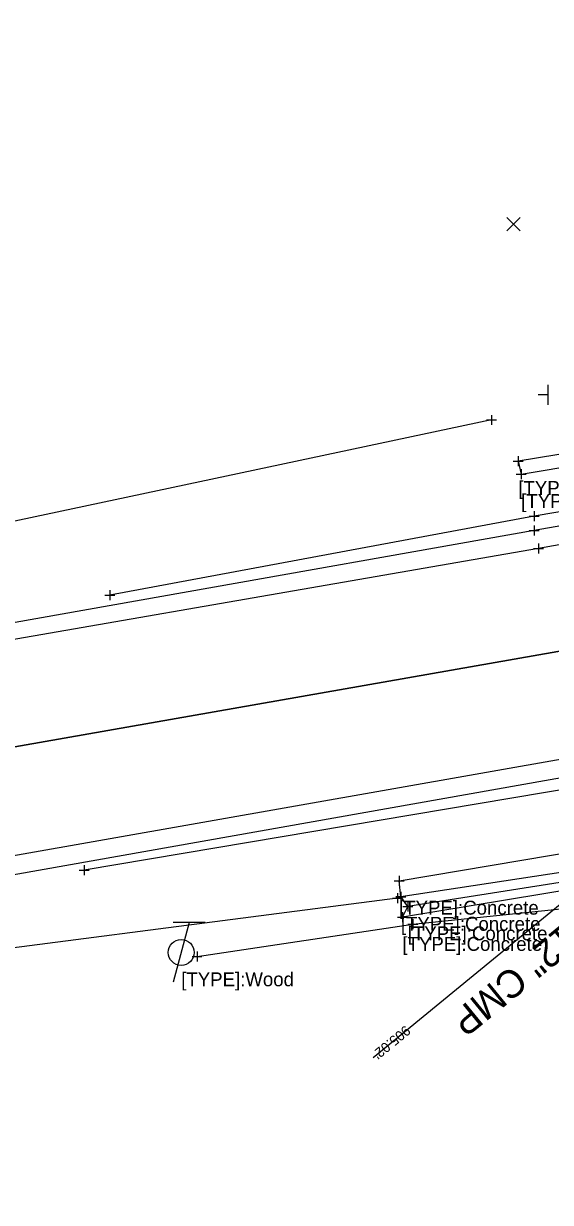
# Model space of a CAD drawing. Extents: x 1386013 to 1389776, y 604170 to 607009.
# Drawn here: x 1388473.5 to 1388526.5, y 604949.8 to 605068.3 of the extents above; entities that cross this region are included whole.
import ezdxf

# ---------------------------------------------------------------- set-up
doc = ezdxf.new("R2010")
doc.units = 0
for name, color, linetype in [('DR_X_Headwall', 7, 'Continuous'), ('DR_X_Storm_Sewer', 7, 'Continuous'), ('DR_X_Text', 7, 'Continuous'), ('DV_X_Text', 7, 'Continuous'), ('PM_X_CL_Double_Solid', 7, 'Continuous'), ('PV_X_COP', 7, 'Continuous'), ('PV_X_EOP', 7, 'Continuous'), ('PV_X_Shoulder', 7, 'Continuous'), ('RD_X_Concrete_Pad', 7, 'Continuous'), ('RD_X_GR_Lt', 7, 'Continuous'), ('RD_X_GR_Rt', 7, 'Continuous'), ('SC_Scratch1', 7, 'Continuous'), ('SV_X_Break_Lines', 7, 'Continuous'), ('SV_X_Random_Point', 7, 'Continuous'), ('SV_X_Text', 7, 'Continuous'), ('SV_X_Toe_of_Slope', 7, 'Continuous'), ('UT_X_Telecom_Cells', 7, 'Continuous')]:
    doc.layers.add(name, color=color, linetype=linetype)

msp = doc.modelspace()

# ---------------------------------------------------------------- linework, layer by layer
at = {"layer": 'DR_X_Headwall'}
msp.add_lwpolyline([(1388523.22, 605024.36), (1388523.51, 605023.05), (1388554.92, 605028.29), (1388554.72, 605029.52)], close=True, dxfattribs=at)
at = {"layer": 'DR_X_Storm_Sewer'}
msp.add_line((1388532.96, 604984.31), (1388508.62, 604964.38), dxfattribs=at)
at = {"layer": 'DV_X_Text'}
for p, q in [((1388520.02, 605028.49), (1388521.02, 605028.49)), ((1388520.52, 605028.99), (1388520.52, 605027.99)), ((1388520.52, 605028.49), (1388520.52, 605028.49)), ((1388523.22, 605024.86), (1388523.22, 605023.86)), ((1388522.72, 605024.36), (1388523.72, 605024.36)), ((1388523.22, 605024.36), (1388523.22, 605024.36)), ((1388523.51, 605023.55), (1388523.51, 605022.55)), ((1388523.01, 605023.05), (1388524.01, 605023.05)), ((1388523.51, 605023.05), (1388523.51, 605023.05)), ((1388524.31, 605018.82), (1388525.31, 605018.82)), ((1388524.81, 605019.32), (1388524.81, 605018.32)), ((1388524.81, 605018.82), (1388524.81, 605018.82)), ((1388524.83, 605017.88), (1388524.83, 605016.88)), ((1388524.33, 605017.38), (1388525.33, 605017.38)), ((1388524.83, 605017.38), (1388524.83, 605017.38)), ((1388524.76, 605015.57), (1388525.76, 605015.57)), ((1388525.26, 605016.07), (1388525.26, 605015.07)), ((1388525.26, 605015.57), (1388525.26, 605015.57)), ((1388481.63, 605010.89), (1388482.63, 605010.89)), ((1388482.13, 605011.39), (1388482.13, 605010.39)), ((1388482.13, 605010.89), (1388482.13, 605010.89)), ((1388479.07, 604983.23), (1388480.07, 604983.23)), ((1388479.57, 604983.73), (1388479.57, 604982.73)), ((1388479.57, 604983.23), (1388479.57, 604983.23)), ((1388510.73, 604982.16), (1388511.73, 604982.16)), ((1388511.23, 604982.66), (1388511.23, 604981.66)), ((1388511.23, 604982.16), (1388511.23, 604982.16)), ((1388511.07, 604980.92), (1388511.07, 604979.92)), ((1388511.41, 604981.07), (1388511.41, 604980.07)), ((1388511.41, 604981.04), (1388511.41, 604980.04)), ((1388510.57, 604980.42), (1388511.57, 604980.42)), ((1388510.91, 604980.57), (1388511.91, 604980.57)), ((1388510.91, 604980.54), (1388511.91, 604980.54)), ((1388511.07, 604980.42), (1388511.07, 604980.42)), ((1388511.41, 604980.57), (1388511.41, 604980.57)), ((1388511.41, 604980.54), (1388511.41, 604980.54)), ((1388512.1, 604980.09), (1388512.1, 604979.09)), ((1388512.11, 604980.08), (1388512.11, 604979.08)), ((1388511.07, 604978.52), (1388512.07, 604978.52)), ((1388511.57, 604979.02), (1388511.57, 604978.02)), ((1388511.57, 604978.52), (1388511.57, 604978.52)), ((1388511.6, 604979.59), (1388512.6, 604979.59)), ((1388511.61, 604979.58), (1388512.61, 604979.58)), ((1388512.1, 604979.59), (1388512.1, 604979.59)), ((1388512.11, 604979.58), (1388512.11, 604979.58)), ((1388512.12, 604977.8), (1388513.12, 604977.8)), ((1388512.62, 604978.3), (1388512.62, 604977.3)), ((1388512.62, 604977.8), (1388512.62, 604977.8)), ((1388490.91, 604975.05), (1388490.91, 604974.05)), ((1388490.41, 604974.55), (1388491.41, 604974.55)), ((1388490.91, 604974.55), (1388490.91, 604974.55))]:
    msp.add_line(p, q, dxfattribs=at)
at = {"layer": 'PM_X_CL_Double_Solid'}
msp.add_lwpolyline([(1387998.85, 604914.97), (1388072.27, 604927.44), (1388150.34, 604940.54), (1388219.83, 604952.56), (1388327.21, 604971.05), (1388378.93, 604979.71), (1388451.75, 604991.99), (1388527.19, 605005.2), (1388605.28, 605019.17), (1388650.04, 605026.96), (1388727.22, 605040.35), (1388785.55, 605050.58), (1388850.55, 605062.12), (1388924.49, 605075.02), (1388990.9, 605086.8), (1389068.68, 605100.88), (1389141.9, 605114.3), (1389207.53, 605126.39), (1389280.37, 605139.49)], dxfattribs=at)
at = {"layer": 'PV_X_COP'}
msp.add_lwpolyline([(1389280.37, 605139.49), (1389207.53, 605126.39), (1389141.9, 605114.3), (1389068.68, 605100.88), (1388990.9, 605086.8), (1388924.49, 605075.02), (1388850.55, 605062.12), (1388785.55, 605050.58), (1388727.22, 605040.35), (1388650.04, 605026.96), (1388605.28, 605019.17), (1388527.19, 605005.2), (1388451.75, 604991.99), (1388378.93, 604979.71), (1388327.21, 604971.05), (1388219.83, 604952.56), (1388150.34, 604940.54), (1388072.27, 604927.44), (1387998.85, 604914.97)], dxfattribs=at)
at = {"layer": 'PV_X_EOP'}
for points in [[(1389278.61, 605149.89), (1389205.62, 605136.54), (1389139.99, 605124.61), (1389067.04, 605111.39), (1388989.39, 605097.25), (1388922.83, 605085.43), (1388849.86, 605072.55), (1388784.25, 605061.08), (1388726.08, 605051), (1388647.73, 605037.35), (1388603.87, 605029.52), (1388525.26, 605015.57), (1388450.62, 605002.62), (1388377.29, 604990.08), (1388325.54, 604981.41), (1388218.94, 604963.01), (1388149.68, 604951.27), (1388070.9, 604937.92), (1387997.67, 604925.46)], [(1389281.27, 605129.06), (1389208.5, 605115.45), (1389143.42, 605103.48), (1389070.14, 605089.92), (1388993.29, 605076.1), (1388925.01, 605063.95), (1388851.7, 605051.17), (1388786.31, 605039.62), (1388729.8, 605029.75), (1388651.59, 605016.29), (1388606.27, 605008.43), (1388528.77, 604994.59), (1388453.6, 604981.36), (1388380.25, 604968.93), (1388328.49, 604960.28), (1388221.37, 604941.87), (1388151.14, 604929.78), (1388073.48, 604916.74), (1388000.2, 604904.18)]]:
    msp.add_lwpolyline(points, dxfattribs=at)
at = {"layer": 'PV_X_Shoulder'}
for points in [[(1389278.32, 605151.38), (1389205.26, 605138.27), (1389139.52, 605126.2), (1389066.77, 605113.2), (1388989.16, 605098.99), (1388922.81, 605087.13), (1388849.4, 605074.38), (1388802.29, 605066.59), (1388793.59, 605066.34), (1388786.16, 605070.01), (1388734.23, 605060.31), (1388725.78, 605053.3), (1388647.71, 605038.75), (1388603.54, 605031.12), (1388524.83, 605017.38), (1388449.88, 605004.12), (1388377.38, 604991.89), (1388326.15, 604983.28), (1388218.46, 604964.95), (1388149.62, 604953.16), (1388070.88, 604939.75), (1387997.08, 604927.24)], [(1389070.3, 605088.44), (1388993.76, 605074.51), (1388925.14, 605062.29), (1388851.88, 605049.71), (1388786.62, 605037.96), (1388729.92, 605028.26), (1388651.51, 605014.41), (1388606.72, 605006.79), (1388529.08, 604992.77), (1388453.76, 604979.45), (1388380.57, 604967.56), (1388328.47, 604958.58), (1388293.07, 604951.05), (1388291.51, 604952.1), (1388221.65, 604940.36), (1388151.37, 604928.17), (1388118.45, 604921.92), (1388113.87, 604918.91), (1388113.3, 604917.2), (1388092.34, 604913.82), (1388086.61, 604916.75), (1388073.66, 604915.38), (1388000.63, 604902.69)]]:
    msp.add_lwpolyline(points, dxfattribs=at)
at = {"layer": 'RD_X_Concrete_Pad'}
msp.add_lwpolyline([(1388511.57, 604978.52), (1388512.11, 604979.58), (1388511.41, 604980.54), (1388511.23, 604982.16), (1388529.73, 604985.28), (1388532, 604984.61), (1388532.17, 604983.76), (1388532.48, 604981.97)], close=True, dxfattribs=at)
at = {"layer": 'RD_X_GR_Lt'}
msp.add_lwpolyline([(1388601, 605005.26), (1388529.13, 604991.56), (1388479.57, 604983.23)], dxfattribs=at)
at = {"layer": 'RD_X_GR_Rt'}
msp.add_lwpolyline([(1388603.57, 605032.16), (1388524.81, 605018.82), (1388482.13, 605010.89)], dxfattribs=at)
at = {"layer": 'SV_X_Break_Lines'}
msp.add_lwpolyline([(1388490.91, 604974.55), (1388512.62, 604977.8), (1388528.48, 604979.46), (1388546.37, 604982.88), (1388560.48, 604985.3)], dxfattribs=at)
msp.add_lwpolyline([(1388512.1, 604979.59), (1388511.41, 604980.57), (1388532.14, 604983.74), (1388532.34, 604982.77)], close=True, dxfattribs=at)
at = {"layer": 'SV_X_Random_Point'}
for p, q in [((1388522.07, 605047.52), (1388523.4, 605048.85)), ((1388522.07, 605048.85), (1388523.4, 605047.52))]:
    msp.add_line(p, q, dxfattribs=at)
at = {"layer": 'SV_X_Toe_of_Slope'}
for points in [[(1388520.52, 605028.49), (1388449.06, 605013.33), (1388396.7, 604999.43)], [(1388511.07, 604980.42), (1388454.61, 604973.1), (1388381.41, 604961.65), (1388323.48, 604950.37)]]:
    msp.add_lwpolyline(points, dxfattribs=at)
at = {"layer": 'UT_X_Telecom_Cells'}
for p, q in [((1388526.22, 605030.03), (1388526.22, 605032.03)), ((1388526.22, 605031.03), (1388525.22, 605031.03)), ((1388490.12, 604977.96), (1388488.51, 604971.96)), ((1388491.72, 604977.96), (1388488.52, 604977.96))]:
    msp.add_line(p, q, dxfattribs=at)
msp.add_circle((1388489.32, 604974.96), 1.3, dxfattribs=at)

# ---------------------------------------------------------------- texts
at = {"layer": 'DR_X_Text'}
msp.add_text('12" CMP', height=2.8, rotation=219.3196, dxfattribs=at).set_placement((1388527.7, 604977.94))
at = {"layer": 'SC_Scratch1'}
msp.add_text("905.02'", height=1, rotation=219.3196, dxfattribs=at).set_placement((1388511.86, 604967.68))
at = {"layer": 'SV_X_Text'}
for s, p in [('[TYPE]:Concrete', (1388523.22, 605020.96)), ('[TYPE]:Concrete', (1388523.51, 605019.65)), ('[TYPE]:Concrete', (1388511.23, 604978.76)), ('[TYPE]:Concrete', (1388511.41, 604977.14)), ('[TYPE]:Concrete', (1388512.11, 604976.18)), ('[TYPE]:Concrete', (1388511.57, 604975.12)), ('[TYPE]:Wood', (1388489.32, 604971.56))]:
    msp.add_text(s, height=1.4, dxfattribs=at).set_placement(p)

doc.saveas('drawing.dxf')
